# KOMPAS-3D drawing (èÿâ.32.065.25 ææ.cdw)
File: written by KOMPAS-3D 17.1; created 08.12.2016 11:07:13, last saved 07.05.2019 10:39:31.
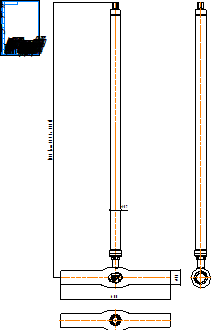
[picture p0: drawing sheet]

Sheet 1: A4, portrait

Title block, sheet 1: name: КШГ.32.065.25 СС; material: Внимание! Данный продукт является объектом авторского права ООО «Торговый Дом АДЛ». / Запрещается изменение, копирование, распространение / (в том числе путем копирования на другие сайты и ресурсы в Интернете) / или любое иное использование информации и объектов без предварительного / согласия правообладателя (ООО «Торговый Дом АДЛ»).; sheets: 1; organisation: ООО "Торговый дом АДЛ"; sheet format: A4; stored path: C:\Users\kka\KOMPAS_Work\Модели кранов для исследований\DN65\С удлинением\КШГ.35.050.25 СС ГЧ _ Шаровой кран БИВАЛ Ду50 Ру2,5 МПа полнопроходной под приварку, c удлинением штока H=950 Габаритный чертеж Lстр600.cdw; drawn by: Климкович К.А.; drawn by, date: 07.12.16

Views: Вид 1, Проекционный вид 2
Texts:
  Klimkovich
  ADL
  (от 287 до 5000)
Dimensions and other numbers on the sheet: 600; 76; 1500; 57; 1:1; 1; 07.12.16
